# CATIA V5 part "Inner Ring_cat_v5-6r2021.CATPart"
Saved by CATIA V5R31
Part number: Inner Ring
Bounding box of the stored display mesh (mm): x -69.981 to 69.981, y 0 to 50, z -69.908 to 69.908
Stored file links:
  D:\PROJECTS\Project 2021\US EDITION\CATIA V5 6R 2021\Resources\Tutorial Files\c16_catia_v5_6r2021_tut\Bearing\Inner Ring_cat_v5-6r2019.CATPart
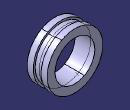
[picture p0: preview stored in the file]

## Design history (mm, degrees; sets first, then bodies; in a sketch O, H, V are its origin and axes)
Body1 (main body)
  Sketch1 on yz-plane, origin (0, 0, 0), H (0, 1, 0), V (0, 0, 1)
    point P1 (0, 50)
    line L1 (0, 50) -> (0, 70)
    line L2 (0, 70) -> (15, 70)
    line L3 (15, 70) -> (15, 65)
    line L4 (15, 65) -> (35, 65)
    line L5 (35, 65) -> (35, 70)
    point P6 (35, 70)
    line L6 (35, 70) -> (50, 70)
    line L7 (50, 70) -> (50, 50)
    line L8 (50, 50) -> (0, 50)
    distance L8 H = 50
    length L8 = 50
    length L6 = 15
    length L2 = 15
    length L7 = 20
    distance L8 L4 = 15
    coincidence: P1 V, P6 L2
    vertical: L1 V, L3 V, L5 V, L7 V
    horizontal: L2 H, L4 H, L6 H, L8 H
  Shaft1: profile Sketch1, axis Sketch1.H, angle 360
  Plane1: type Offset, RefPlane face of Shaft1 from Sketch1.L3, Offset 10, reversed
  Sketch2 on Plane1, origin (0, 25, 0), H (1, 0, 0), V (0, 0, 1)
    projected circle E1 centre (0, 0) radius 65 from edge [face of Shaft1 from Sketch1.L4 | face of Shaft1 from Sketch1.L5]
  Point1: type OnCurve, Support Sketch2, RefPoint {extremum Reference Sketch2, Direction (1, 2, 3)}, Length 192.617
